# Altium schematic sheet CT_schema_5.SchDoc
size 255 x 159 mm
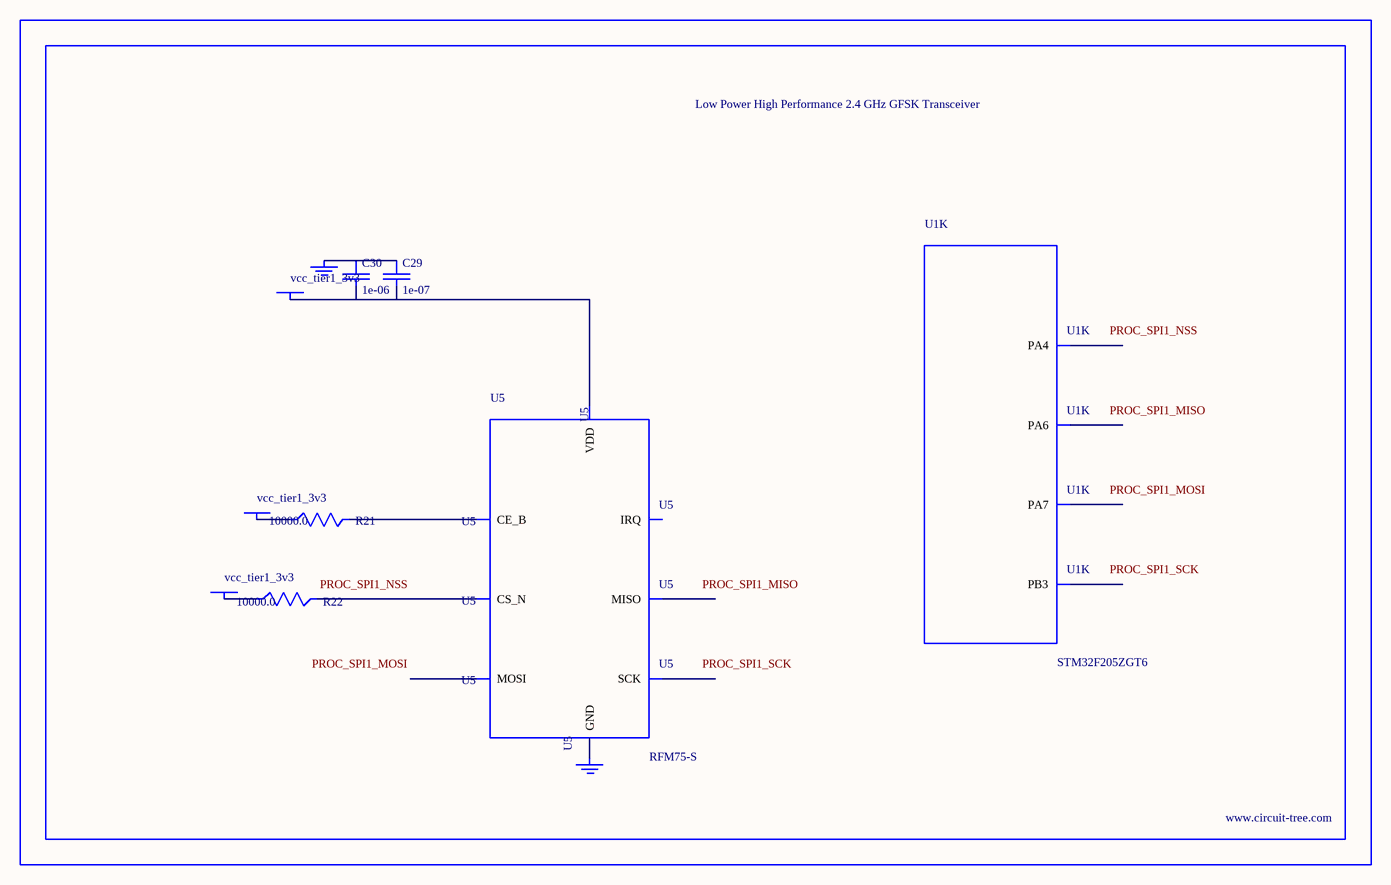
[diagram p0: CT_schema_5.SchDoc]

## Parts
BORDER4  (no value)
C29  1e-07  [C0402]
C30  1e-06  [C0603]
GND_INSTANCE_4_0  (no value)
GND_INSTANCE_4_1  (no value)
POWER_INSTANCE_4_0  vcc_tier1_3v3
POWER_INSTANCE_4_1  vcc_tier1_3v3
POWER_INSTANCE_4_2  vcc_tier1_3v3
R21  10000.0  [R0603]
R22  10000.0  [R0603]
U1  STM32F205ZGT6  [LQFP144]  (part K of 12)
U5  RFM75-S  [RFM75-S]

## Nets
NetC29_1: C29.1 C30.1 GND_INSTANCE_4_0.0(GND)
NetC29_2: C29.2 C30.2 POWER_INSTANCE_4_0.0(PWR) U5.2(VDD)
NetGND_INSTANCE_4_1_0: GND_INSTANCE_4_1.0(GND) U5.1(GND)
NetPOWER_INSTANCE_4_1_0: POWER_INSTANCE_4_1.0(PWR) R21.1
NetPOWER_INSTANCE_4_2_0: POWER_INSTANCE_4_2.0(PWR) R22.1
NetR21_2: R21.2 U5.3(CE_B)
NetR22_2: R22.2 U5.4(CS_N)

Not connected (* = marked no-connect by the designer): U1 40(PA4) 42(PA6) 43(PA7) 133(PB3); U5 5(SCK) 6(MOSI) 7(MISO) 8(IRQ)

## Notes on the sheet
- Labels drawn without touching a wire or pin: PROC_SPI1_MISO, PROC_SPI1_MOSI, PROC_SPI1_NSS, PROC_SPI1_SCK

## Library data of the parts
BORDER4 = BORDER_PAGE4
C29 = C0402C104K3RACTU
C30 = C0603C105K3RACTU
GND_INSTANCE_4_0 GND_INSTANCE_4_1 = GND
POWER_INSTANCE_4_0-POWER_INSTANCE_4_2 = PWR
R21 R22 = RC0603JR-0710KL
